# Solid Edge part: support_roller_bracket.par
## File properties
Accuracy: 0.99
Title: Support roller bracket
Author: Abhinav Rai
Template: Normal.par
Last saved by: CADCIM
Revision: 19
Application: Solid Edge
Material: aluminum
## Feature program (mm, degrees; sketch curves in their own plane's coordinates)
sketch for "unnamed Protrusion 1" #1 plane through (0, 0, 0) normal (0, -1, 0) x-axis (1, 0, 0)
  circle centre (0, -138.9237) radius 3.81
sketch for "unnamed Protrusion 1" #2 plane through (0, 0, 0) normal (0, -1, 0) x-axis (1, 0, 0)
  line (143.637, -99.9249) -> (-143.637, -99.9249)
  line (-143.637, -99.9249) -> (-143.637, -115.1647)
  line (-143.637, -115.1647) -> (-61.0846, -156.7704)
  line (-61.0846, -156.7704) -> (-61.0846, -162.9363)
  line (-61.0846, -162.9363) -> (61.0846, -162.9363)
  line (61.0846, -156.7704) -> (61.0846, -162.9363)
  line (143.637, -115.1647) -> (61.0846, -156.7704)
  line (143.637, -99.9249) -> (143.637, -115.1647)
  dimension (linear) = 143.637
extrude "unnamed Protrusion 1" add finite 101.6 symmetric
fillet "Round_1" radius 31.75
fillet "Round_2" radius 6.35
sketch for "unnamed Protrusion 2" plane through (0, 0, 67.2512) normal (1, 0, 0) x-axis (0, 1, 0)
  arc centre (-23.4135, -61.792) radius 19.05 from (-23.4135, -42.742) to (-42.405, -60.3002) ccw
  line (-50.8, -167.1761) -> (-42.405, -60.3002)
  line (-50.8, -167.1761) -> (50.8, -167.1761)
  line (45.7777, -60.8928) -> (50.8, -167.1761)
  arc centre (26.749, -61.792) radius 19.05 from (26.749, -42.742) to (45.7777, -60.8928) cw
  line (19.05, -42.742) -> (26.749, -42.742)
  line (19.05, -64.967) -> (19.05, -42.742)
  arc centre (0, -64.967) radius 19.05 from (-19.05, -64.967) to (19.05, -64.967) ccw
  line (-19.05, -42.742) -> (-19.05, -64.967)
  line (-23.4135, -42.742) -> (-19.05, -42.742)
extrude "unnamed Protrusion 2" add to key point symmetric
sketch for "ExtrudedCutout_1" plane through (0, 0, 0) normal (0, -1, 0) x-axis (1, 0, 0)
  line (-128.3193, 24.5092) -> (125.6319, 24.5092)
  line (125.6319, 24.5092) -> (125.6319, -99.9249)
  line (125.6319, -99.9249) -> (-128.3193, -99.9249)
  line (-128.3193, -99.9249) -> (-128.3193, 24.5092)
extrude "ExtrudedCutout_1" cut finite 203.2 symmetric
chamfer "Chamfer_1" setback 5.08
rib "Rib_1"  Thickness = 25.4 mm
mirror "unnamed Mirror 1" of "Rib_1" about plane through (0, 0, 0) normal (1, 0, 0)
rib "unnamed Rib 1"
sketch for "Hole_1" plane through (0.1259, 0, -162.9363) normal (0, 0, -1) x-axis (-1, 0, 0)
  hole centre (0.1259, 0) bore radius 25.4
hole "Hole_1" diameter 50.8 through
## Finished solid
Body 1: solid body, 55 faces, 142 edges, 86 vertices.
  Faces by surface: plane 38, cylinder 17
  Edges by curve: line 106, circle 34, intersection 2
Bounding box of the edges (mm): 379.121 x 101.600 x 187.446, from (-189.5605, -50.8, -162.9363) to (189.5605, 50.8, 24.5092).
Cylindrical faces by radius (mm): R3.81 x2, R6.35 x2, R19.05 x6, R25.4 x1, R31.75 x4, R55.372 x2
Planar faces by outward normal: +x 4, +y 5, +z 5, -x 4, -y 5, -z 1, oblique 14
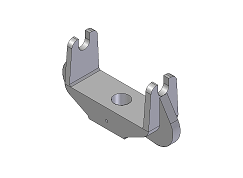
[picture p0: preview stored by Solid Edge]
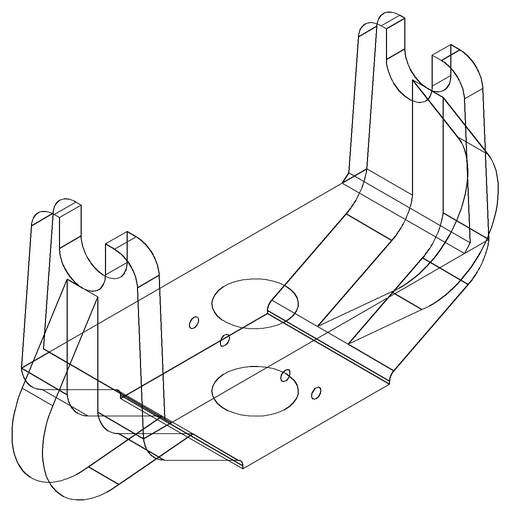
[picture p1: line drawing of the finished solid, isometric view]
